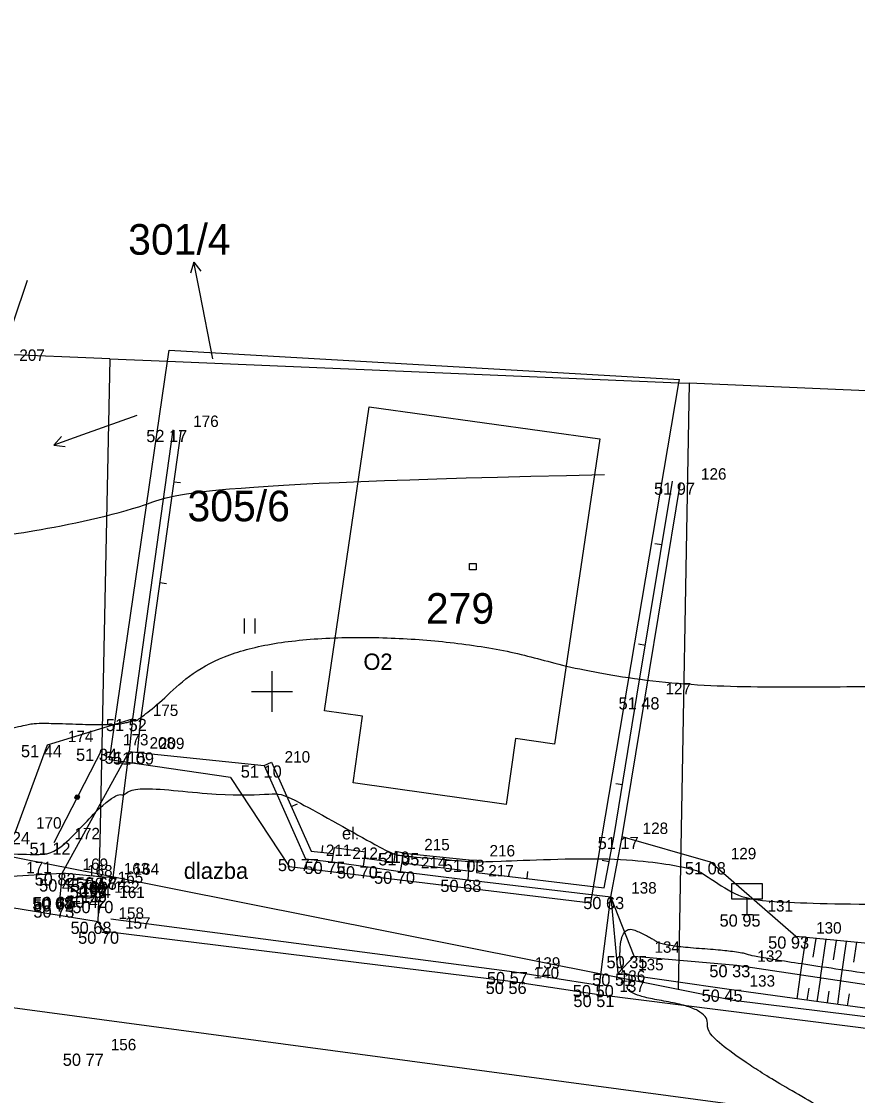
# Model space of a CAD drawing. Extents: x -704057 to -703795, y -1008732 to -1008584.
# Drawn here: x -703931.14 to -703910.66, y -1008659.9 to -1008633.59 of the extents above; entities that cross this region are included whole.
import ezdxf

# ---------------------------------------------------------------- set-up
doc = ezdxf.new("R2010")
doc.units = 0
for name, color, linetype in [('Z_body', 7, 'Continuous'), ('Z_body_cisla', 7, 'Continuous'), ('Z_body_vysky', 7, 'Continuous'), ('Z_chodnik', 7, 'Continuous'), ('Z_chody', 7, 'Continuous'), ('Z_dopravni_znaceni', 7, 'Continuous'), ('Z_hekt_sit', 7, 'Continuous'), ('Z_katastr_cisla_pozemkove', 7, 'Continuous'), ('Z_katastr_cisla_stavebni', 7, 'Continuous'), ('Z_katastr_hranice', 7, 'Continuous'), ('Z_katastr_hranice_KU', 7, 'Continuous'), ('Z_katastr_znacky', 7, 'Continuous'), ('Z_komunikace_zpevn_pl', 7, 'Continuous'), ('Z_oploceni', 7, 'Continuous'), ('Z_popis', 7, 'Continuous'), ('Z_propustek', 7, 'Continuous'), ('Z_rozhrani_zpevn', 7, 'Continuous'), ('Z_site_pilire', 7, 'Continuous'), ('Z_teren_hrany_paty', 7, 'Continuous'), ('Z_vrstevnice_popis', 7, 'Continuous'), ('Z_vrstevnice_vedlejsi', 7, 'Continuous'), ('Z_vstupy', 7, 'Continuous'), ('Z_zabradli', 7, 'Continuous'), ('Z_zelen_souvisla', 7, 'Continuous')]:
    doc.layers.add(name, color=color, linetype=linetype)

# ---------------------------------------------------------------- blocks, each defined once
blk = doc.blocks.new('POINT_DISPLAY')
blk.add_line((0, 0), (0, 0))
blk = doc.blocks.new('Z210')
blk.add_line((0, 0), (0, 0.17))
blk = doc.blocks.new('Z530')
for p, q in [((-0.05, 0.03), (-0.03, 0.05)), ((-0.05, -0.03), (-0.05, 0.03)), ((-0.03, 0.05), (0.03, 0.05)), ((-0.03, -0.03), (-0.03, 0.03)), ((-0.03, 0.03), (0.03, 0.03)), ((-0.03, -0.03), (0.03, 0.03)), ((0.03, 0.05), (0.05, 0.03)), ((0.03, 0.03), (0.03, -0.03)), ((0.05, 0.03), (0.05, -0.03)), ((-0.03, -0.05), (-0.05, -0.03)), ((0.03, -0.03), (-0.03, -0.03)), ((0.03, -0.05), (-0.03, -0.05)), ((0.05, -0.03), (0.03, -0.05))]:
    blk.add_line(p, q)
blk = doc.blocks.new('Z526')
for p, q in [((0.38, 0.75), (-0.38, 0.75)), ((-0.38, 0.75), (-0.38, 0.38)), ((0.38, 0.38), (0.38, 0.75)), ((-0.38, 0.38), (0.38, 0.38)), ((0, 0), (0, 0.38)), ((-0.13, 0), (0.13, 0))]:
    blk.add_line(p, q)
blk = doc.blocks.new('Z402')
for p, q in [((-0.03, 0.03), (0.05, 0.03)), ((-0.03, -0.05), (-0.03, 0.03)), ((0.05, 0.03), (0.05, -0.05)), ((0.05, -0.05), (-0.03, -0.05))]:
    blk.add_line(p, q)
blk = doc.blocks.new('Z61')
for p, q in [((0, 0.75), (-0.13, 0.5)), ((0, 0), (0, 0.75)), ((0, 0.75), (0.13, 0.5))]:
    blk.add_line(p, q)
blk = doc.blocks.new('Z306')
for p, q in [((-0.13, 0.17), (-0.13, -0.2)), ((0.13, 0.17), (0.13, -0.2))]:
    blk.add_line(p, q)

msp = doc.modelspace()

# ---------------------------------------------------------------- linework, layer by layer
at = {"layer": 'Z_chodnik'}
for p, q in [((-703928.89, -1008654.56), (-703928.5, -1008651.47)), ((-703916.98, -1008657.19), (-703916.7, -1008655.03)), ((-703929.26, -1008655.64), (-703929.24, -1008655.13)), ((-703916.99, -1008657.43), (-703916.98, -1008657.19))]:
    msp.add_line(p, q, dxfattribs=at)
at = {"layer": 'Z_chody'}
for p, q in [((-703921.81, -1008654.2), (-703920.19, -1008654.39)), ((-703921.85, -1008654.41), (-703920.2, -1008654.61))]:
    msp.add_line(p, q, dxfattribs=at)
at = {"layer": 'Z_hekt_sit'}
for p, q in [((-703925, -1008649.5), (-703925, -1008650.5)), ((-703925.5, -1008650), (-703924.5, -1008650))]:
    msp.add_line(p, q, dxfattribs=at)
at = {"layer": 'Z_katastr_cisla_pozemkove'}
for points in [[(-703926.45, -1008641.85), (-703926.77, -1008640.22)], [(-703928.31, -1008643.24), (-703929.64, -1008643.71)]]:
    msp.add_lwpolyline(points, dxfattribs=at)
at = {"layer": 'Z_katastr_hranice'}
for p, q in [((-703928.97, -1008641.85), (-703944.54, -1008641.19)), ((-703927.56, -1008641.91), (-703927.52, -1008641.64)), ((-703927.52, -1008641.64), (-703915.02, -1008642.36)), ((-703928.97, -1008641.85), (-703929.22, -1008653.69)), ((-703928.98, -1008651.67), (-703927.56, -1008641.91)), ((-703928.97, -1008641.85), (-703927.56, -1008641.91)), ((-703927.56, -1008641.91), (-703915.03, -1008642.44)), ((-703917.19, -1008655.18), (-703915.03, -1008642.44)), ((-703915.03, -1008642.44), (-703915.02, -1008642.36)), ((-703915.03, -1008642.44), (-703914.78, -1008642.45)), ((-703914.78, -1008642.45), (-703915.02, -1008655.64)), ((-703892.76, -1008643.39), (-703914.78, -1008642.45)), ((-703923.71, -1008650.47), (-703922.62, -1008643.03)), ((-703922.62, -1008643.03), (-703916.97, -1008643.81)), ((-703916.97, -1008643.81), (-703918.08, -1008651.29)), ((-703922.78, -1008650.6), (-703923.71, -1008650.47)), ((-703923.01, -1008652.24), (-703922.78, -1008650.6)), ((-703919.03, -1008651.15), (-703919.26, -1008652.77)), ((-703918.08, -1008651.29), (-703919.03, -1008651.15)), ((-703944.4, -1008651.45), (-703929.24, -1008654.47)), ((-703926.02, -1008652.11), (-703928.98, -1008651.67)), ((-703926.02, -1008652.11), (-703924.58, -1008654.29)), ((-703919.26, -1008652.77), (-703923.01, -1008652.24)), ((-703929.22, -1008653.69), (-703929.24, -1008654.47)), ((-703924.58, -1008654.29), (-703917.19, -1008655.18)), ((-703929.24, -1008654.47), (-703915.05, -1008657.29)), ((-703915.02, -1008655.64), (-703915.05, -1008657.29)), ((-703915.05, -1008657.29), (-703913.69, -1008657.56)), ((-703913.69, -1008657.56), (-703892.72, -1008660.17))]:
    msp.add_line(p, q, dxfattribs=at)
at = {"layer": 'Z_katastr_hranice_KU'}
msp.add_line((-703947.15, -1008655.63), (-703906.73, -1008661.04), dxfattribs=at)
at = {"layer": 'Z_komunikace_zpevn_pl'}
for p, q in [((-703929.26, -1008655.64), (-703940.41, -1008653.86)), ((-703929.1, -1008655.88), (-703929.26, -1008655.64)), ((-703919.09, -1008657.11), (-703929.1, -1008655.88)), ((-703916.99, -1008657.43), (-703919.09, -1008657.11)), ((-703906.05, -1008658.81), (-703916.99, -1008657.43))]:
    msp.add_line(p, q, dxfattribs=at)
at = {"layer": 'Z_oploceni'}
for p, q in [((-703927.43, -1008643.59), (-703928.42, -1008650.67)), ((-703927.23, -1008643.62), (-703928.22, -1008650.7)), ((-703916.06, -1008650.11), (-703915.19, -1008644.85)), ((-703915.86, -1008650.14), (-703914.99, -1008644.88)), ((-703916.62, -1008653.53), (-703916.06, -1008650.11)), ((-703916.42, -1008653.56), (-703915.86, -1008650.14)), ((-703928.42, -1008650.67), (-703928.5, -1008651.47)), ((-703928.22, -1008650.69), (-703928.3, -1008651.49)), ((-703928.5, -1008651.47), (-703928.27, -1008651.49)), ((-703925.19, -1008651.81), (-703925.01, -1008651.73)), ((-703925.19, -1008651.81), (-703924.18, -1008654.1)), ((-703925.01, -1008651.73), (-703924.04, -1008653.91)), ((-703916.86, -1008654.81), (-703916.62, -1008653.53)), ((-703916.7, -1008655.03), (-703916.42, -1008653.56)), ((-703924.04, -1008653.91), (-703923.5, -1008653.97)), ((-703922.01, -1008654.18), (-703921.97, -1008653.92)), ((-703921.77, -1008653.96), (-703921.97, -1008653.92)), ((-703921.85, -1008654.41), (-703921.77, -1008653.96)), ((-703924.18, -1008654.1), (-703923.53, -1008654.17)), ((-703922.76, -1008654.28), (-703921.85, -1008654.41)), ((-703922.73, -1008654.08), (-703922.01, -1008654.18)), ((-703920.17, -1008654.12), (-703920.2, -1008654.61)), ((-703920.17, -1008654.12), (-703919.97, -1008654.13)), ((-703919.97, -1008654.13), (-703919.99, -1008654.43)), ((-703919.99, -1008654.43), (-703916.86, -1008654.81)), ((-703920.2, -1008654.61), (-703916.7, -1008655.03))]:
    msp.add_line(p, q, dxfattribs=at)
at = {"layer": 'Z_propustek'}
for p, q in [((-703929.13, -1008654.55), (-703929.37, -1008655)), ((-703929.24, -1008655.13), (-703928.89, -1008654.56)), ((-703928.89, -1008654.56), (-703929.13, -1008654.55)), ((-703930.18, -1008655.09), (-703929.37, -1008655)), ((-703930.17, -1008655.24), (-703930.18, -1008655.09)), ((-703930.17, -1008655.24), (-703929.24, -1008655.13))]:
    msp.add_line(p, q, dxfattribs=at)
at = {"layer": 'Z_rozhrani_zpevn'}
for p, q in [((-703928.95, -1008655.57), (-703919.06, -1008656.87)), ((-703919.06, -1008656.87), (-703916.98, -1008657.19))]:
    msp.add_line(p, q, dxfattribs=at)
at = {"layer": 'Z_site_pilire'}
for p, q in [((-703923.48, -1008653.82), (-703923.53, -1008654.17)), ((-703923.48, -1008653.82), (-703922.71, -1008653.93)), ((-703922.76, -1008654.28), (-703922.71, -1008653.93)), ((-703923.53, -1008654.17), (-703922.76, -1008654.28))]:
    msp.add_line(p, q, dxfattribs=at)
at = {"layer": 'Z_teren_hrany_paty'}
for p, q in [((-703930.5, -1008651.31), (-703928.42, -1008650.67)), ((-703931.28, -1008653.44), (-703930.5, -1008651.31)), ((-703930.14, -1008654.45), (-703928.5, -1008651.47)), ((-703914.26, -1008654.18), (-703916.42, -1008653.56)), ((-703912.17, -1008656), (-703914.26, -1008654.18)), ((-703931.52, -1008654.53), (-703930.14, -1008654.45)), ((-703930.14, -1008654.45), (-703930.2, -1008655.04)), ((-703929.13, -1008654.55), (-703930.14, -1008654.45)), ((-703930.18, -1008655.09), (-703930.2, -1008655.04)), ((-703916.7, -1008655.03), (-703916.53, -1008656.91)), ((-703916.13, -1008656.48), (-703916.7, -1008655.03)), ((-703905.76, -1008656.62), (-703912.17, -1008656)), ((-703911.92, -1008656.02), (-703912.06, -1008656.93)), ((-703911.68, -1008656.05), (-703911.75, -1008656.51)), ((-703911.43, -1008656.07), (-703911.57, -1008657.01)), ((-703911.18, -1008656.1), (-703911.25, -1008656.57)), ((-703910.93, -1008656.12), (-703911.07, -1008657.08)), ((-703910.68, -1008656.14), (-703910.75, -1008656.63)), ((-703916.53, -1008656.91), (-703916.13, -1008656.48)), ((-703916.13, -1008656.48), (-703913.61, -1008656.7)), ((-703913.8, -1008657.3), (-703916.53, -1008656.91)), ((-703913.61, -1008656.7), (-703905.86, -1008657.87)), ((-703912.13, -1008657.53), (-703912.05, -1008656.94)), ((-703911.64, -1008657.6), (-703911.55, -1008657.01)), ((-703911.14, -1008657.66), (-703911.06, -1008657.09)), ((-703905.9, -1008658.38), (-703913.8, -1008657.3)), ((-703911.89, -1008657.56), (-703911.84, -1008657.27)), ((-703911.39, -1008657.63), (-703911.35, -1008657.34)), ((-703910.9, -1008657.7), (-703910.85, -1008657.41))]:
    msp.add_line(p, q, dxfattribs=at)
at = {"layer": 'Z_vrstevnice_popis'}
for points in [[(-703932.312, -1008646.249), (-703931.974, -1008646.22), (-703931.198, -1008646.162), (-703927.689, -1008645.442), (-703927.074, -1008644.896), (-703916.856, -1008644.687)], [(-703958.782, -1008656.452), (-703958.711, -1008656.345), (-703958.126, -1008655.591), (-703956.246, -1008655.482), (-703959.788, -1008654.246), (-703961.93, -1008651.293), (-703961.78, -1008651.126), (-703959.248, -1008651.187), (-703958.2, -1008651.305), (-703958.136, -1008651.315), (-703958.106, -1008651.318), (-703958.062, -1008651.325), (-703957.976, -1008651.334), (-703949.197, -1008652.35), (-703949.055, -1008652.366), (-703948.978, -1008652.372), (-703948.89, -1008652.368), (-703940.582, -1008653.06), (-703940.108, -1008653.095), (-703933.647, -1008653.758), (-703931.403, -1008653.997), (-703930.745, -1008653.985), (-703930.26, -1008654), (-703929.245, -1008652.825), (-703928.701, -1008652.453), (-703928.643, -1008652.6), (-703928.429, -1008652.279), (-703926.218, -1008652.574), (-703924.884, -1008652.504), (-703924.716, -1008652.484), (-703922.063, -1008653.995), (-703921.911, -1008654.006), (-703921.781, -1008654.024), (-703921.558, -1008654.048), (-703920.173, -1008654.162), (-703919.91, -1008654.188), (-703916.508, -1008654.023), (-703914.694, -1008654.331), (-703914.465, -1008654.432), (-703913.706, -1008654.968), (-703913.145, -1008655.151), (-703910.497, -1008655.228), (-703905.972, -1008655.203), (-703903.752, -1008655.504), (-703902.532, -1008655.695)]]:
    msp.add_open_spline(points, degree=3, dxfattribs=at)
at = {"layer": 'Z_vrstevnice_vedlejsi'}
for points in [[(-704009.362, -1008633.586), (-704007.915, -1008634.739), (-704007.143, -1008635.358), (-704002.876, -1008638.286), (-704002.679, -1008638.43), (-704002.255, -1008638.718), (-704001.165, -1008638.717), (-703995.889, -1008642.289), (-703994.89, -1008642.862), (-703994.417, -1008642.752), (-703993.832, -1008642.719), (-703993.258, -1008640.696), (-703993.341, -1008639.701), (-703993.272, -1008639.432), (-703993.04, -1008638.835), (-703992.99, -1008638.745), (-703990.403, -1008638.423), (-703989.481, -1008638.539), (-703989.058, -1008638.588), (-703989.018, -1008638.516), (-703988.578, -1008638.54), (-703988.475, -1008638.554), (-703988.362, -1008638.685), (-703988.319, -1008638.754), (-703988.294, -1008638.815), (-703986.637, -1008641.391), (-703986.518, -1008641.581), (-703985.267, -1008643.657), (-703984.422, -1008644.955), (-703982.223, -1008646.72), (-703982.083, -1008646.9), (-703980.47, -1008647.779), (-703979.335, -1008647.914), (-703971.793, -1008648.878), (-703969.312, -1008649.063), (-703968.076, -1008649.117), (-703960.948, -1008649.919), (-703959.282, -1008650.186), (-703958.493, -1008650.28), (-703957.367, -1008650.455), (-703955.116, -1008650.684), (-703950.816, -1008651.182), (-703948.3, -1008651.463), (-703946.953, -1008651.576), (-703945.397, -1008651.505), (-703943.023, -1008651.703), (-703939.161, -1008651.987), (-703938.27, -1008652.079), (-703937.191, -1008652.194), (-703934.147, -1008651.524), (-703931.028, -1008650.815), (-703930.717, -1008650.764), (-703928.94, -1008650.83), (-703928.501, -1008650.751), (-703928.424, -1008650.713), (-703928.413, -1008650.708), (-703928.266, -1008650.724), (-703926.027, -1008648.737), (-703920.5, -1008648.624), (-703915.824, -1008649.925), (-703908.88, -1008649.843), (-703904.651, -1008650.155), (-703897.103, -1008651.333), (-703893.743, -1008651.997), (-703889.99, -1008652.252), (-703881.693, -1008653.228), (-703874.656, -1008652.961), (-703868.448, -1008652.365), (-703859.857, -1008652.906), (-703856.36, -1008653.001), (-703843.765, -1008653.766), (-703842.17, -1008653.801), (-703841.143, -1008653.824), (-703831.904, -1008654.28)], [(-703930.067, -1008654.696), (-703930.045, -1008654.58), (-703929.834, -1008654.589), (-703929.209, -1008654.661), (-703929.296, -1008654.862), (-703929.333, -1008655.037), (-703929.576, -1008655.062), (-703929.586, -1008655.024), (-703929.626, -1008655.01), (-703930.062, -1008654.698), (-703930.067, -1008654.696)], [(-703944.218, -1008669.537), (-703942.215, -1008669.847), (-703941.835, -1008669.79), (-703940.983, -1008669.911), (-703940.538, -1008669.059), (-703940.441, -1008669.011), (-703939.659, -1008668.87), (-703938.392, -1008666.573), (-703937.218, -1008665.198), (-703936.994, -1008664.158), (-703936.811, -1008663.182), (-703935.504, -1008662.788), (-703930.851, -1008662.989), (-703930.683, -1008662.945), (-703930.514, -1008662.948), (-703928.53, -1008663.14), (-703926.451, -1008662.869), (-703924.285, -1008662.962), (-703918.453, -1008660.188), (-703917.529, -1008662.583), (-703908.804, -1008661.73), (-703914.417, -1008658.58), (-703914.255, -1008657.775), (-703916.458, -1008657.408), (-703916.075, -1008656.975), (-703916.505, -1008656.883), (-703916.435, -1008655.703), (-703915.746, -1008656.007), (-703915.438, -1008656.225), (-703913.541, -1008656.36), (-703913.202, -1008656.502), (-703907.93, -1008657.256), (-703905.824, -1008657.417), (-703900.033, -1008658.024), (-703894.345, -1008658.848), (-703890.179, -1008659.57), (-703887.702, -1008659.871), (-703882.266, -1008660.175), (-703878.347, -1008660.959), (-703873.149, -1008661.531), (-703869.803, -1008661.293), (-703867.148, -1008661.514), (-703856.66, -1008662.48), (-703848.555, -1008661.935), (-703843.582, -1008661.747), (-703840.018, -1008661.713), (-703835.656, -1008661.182), (-703832.168, -1008661.259), (-703831.497, -1008661.293), (-703819.488, -1008662.346), (-703817.521, -1008662.543), (-703807.841, -1008663.114), (-703805.78, -1008663.132)]]:
    msp.add_open_spline(points, degree=2, dxfattribs=at)
at = {"layer": 'Z_vstupy'}
for p, q in [((-703928.27, -1008651.49), (-703925.19, -1008651.81)), ((-703921.77, -1008653.96), (-703920.17, -1008654.12))]:
    msp.add_line(p, q, dxfattribs=at)
at = {"layer": 'Z_zabradli'}
msp.add_line((-703930.34, -1008653.7), (-703929.15, -1008651.4), dxfattribs=at)
at = {"layer": 'Z_zelen_souvisla'}
msp.add_line((-703931, -1008639.93), (-703931.69, -1008641.97), dxfattribs=at)

# ---------------------------------------------------------------- block references
at = {"layer": 'Z_body'}
for p in [(-703927.43, -1008643.59), (-703914.99, -1008644.88), (-703915.86, -1008650.14), (-703928.42, -1008650.67), (-703930.5, -1008651.31), (-703929.15, -1008651.4), (-703928.5, -1008651.47), (-703928.27, -1008651.49), (-703925.19, -1008651.81), (-703930.34, -1008653.7), (-703916.42, -1008653.56), (-703921.77, -1008653.96), (-703924.18, -1008654.1), (-703923.53, -1008654.17), (-703922.76, -1008654.28), (-703920.17, -1008654.12), (-703914.26, -1008654.18), (-703930.14, -1008654.45), (-703929.13, -1008654.55), (-703928.89, -1008654.56), (-703921.85, -1008654.41), (-703930.03, -1008654.6), (-703929.28, -1008654.76), (-703920.2, -1008654.61), (-703930.2, -1008655.04), (-703930.18, -1008655.09), (-703930.17, -1008655.03), (-703929.37, -1008655), (-703916.7, -1008655.03), (-703930.17, -1008655.24), (-703929.24, -1008655.13), (-703913.36, -1008655.46), (-703929.26, -1008655.64), (-703929.1, -1008655.88), (-703912.17, -1008656), (-703916.13, -1008656.48), (-703919.06, -1008656.87), (-703916.53, -1008656.91), (-703913.61, -1008656.7), (-703919.09, -1008657.11), (-703916.98, -1008657.19), (-703916.99, -1008657.43), (-703913.8, -1008657.3), (-703929.45, -1008658.87)]:
    msp.add_blockref('POINT_DISPLAY', p, dxfattribs=at)
at = {"layer": 'Z_dopravni_znaceni'}
msp.add_blockref('Z526', (-703913.36, -1008655.46), dxfattribs=at)
at = {"layer": 'Z_katastr_cisla_pozemkove'}
for p, rotation in [((-703926.77, -1008640.22), 11.3099), ((-703929.64, -1008643.71), 109.6538)]:
    msp.add_blockref('Z61', p, dxfattribs=dict(at, rotation=rotation))
at = {"layer": 'Z_katastr_znacky', "xscale": 2, "yscale": 2}
msp.add_blockref('Z402', (-703920.1, -1008646.92), dxfattribs=at)
at = {"layer": 'Z_oploceni'}
for p, rotation in [((-703927.41, -1008644.86), -97.99999999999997), ((-703915.45, -1008646.41), 80.6), ((-703927.75, -1008647.33), -97.99999999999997), ((-703915.85, -1008648.87), 80.6), ((-703916.41, -1008652.29), 80.69999999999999), ((-703924.53, -1008652.82), -66.19999999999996), ((-703923.77, -1008653.94), -6.100000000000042), ((-703922.37, -1008654.13), -8.100000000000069), ((-703916.74, -1008654.17), 79.2), ((-703918.75, -1008654.58), -6.80000000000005)]:
    msp.add_blockref('Z210', p, dxfattribs=dict(at, rotation=rotation))
at = {"layer": 'Z_popis'}
msp.add_blockref('Z306', (-703925.55, -1008648.38), dxfattribs=at)
at = {"layer": 'Z_zabradli', "rotation": 62.6}
msp.add_blockref('Z530', (-703929.77, -1008652.59), dxfattribs=at)

# ---------------------------------------------------------------- texts
at = {"layer": 'Z_body_cisla'}
for s, p in [('207', (-703931.19, -1008641.9)), ('176', (-703926.93, -1008643.52)), ('126', (-703914.49, -1008644.81)), ('127', (-703915.36, -1008650.07)), ('175', (-703927.92, -1008650.6)), ('174', (-703930, -1008651.24)), ('173', (-703928.65, -1008651.32)), ('208', (-703928, -1008651.4)), ('209', (-703927.77, -1008651.41)), ('210', (-703924.69, -1008651.74)), ('170', (-703930.78, -1008653.36)), ('128', (-703915.92, -1008653.49)), ('172', (-703929.84, -1008653.62)), ('211', (-703923.68, -1008654.03)), ('215', (-703921.27, -1008653.89)), ('216', (-703919.67, -1008654.04)), ('212', (-703923.03, -1008654.1)), ('213', (-703922.26, -1008654.2)), ('214', (-703921.35, -1008654.33)), ('129', (-703913.76, -1008654.11)), ('171', (-703931.02, -1008654.45)), ('169', (-703929.64, -1008654.37)), ('168', (-703929.53, -1008654.53)), ('163', (-703928.63, -1008654.48)), ('164', (-703928.39, -1008654.49)), ('217', (-703919.7, -1008654.53)), ('165', (-703928.78, -1008654.69)), ('166', (-703929.7, -1008654.96)), ('160', (-703929.68, -1008655.02)), ('167', (-703929.67, -1008654.95)), ('162', (-703928.87, -1008654.93)), ('161', (-703928.74, -1008655.06)), ('138', (-703916.2, -1008654.95)), ('159', (-703929.67, -1008655.16)), ('131', (-703912.86, -1008655.39)), ('158', (-703928.76, -1008655.57)), ('157', (-703928.6, -1008655.81)), ('130', (-703911.67, -1008655.93)), ('134', (-703915.63, -1008656.4)), ('132', (-703913.11, -1008656.62)), ('139', (-703918.56, -1008656.79)), ('135', (-703916.03, -1008656.83)), ('140', (-703918.59, -1008657.03)), ('136', (-703916.48, -1008657.11)), ('133', (-703913.3, -1008657.23)), ('137', (-703916.49, -1008657.36)), ('156', (-703928.95, -1008658.79))]:
    msp.add_text(s, height=0.28, dxfattribs=at).set_placement(p)
at = {"layer": 'Z_body_vysky'}
for s, p in [('52 17', (-703928.08, -1008643.89)), ('51 97', (-703915.64, -1008645.18)), ('51 48', (-703916.51, -1008650.44)), ('51 52', (-703929.07, -1008650.97)), ('51 44', (-703931.15, -1008651.61)), ('51 34', (-703929.8, -1008651.7)), ('51 15', (-703929.1, -1008651.77)), ('51 09', (-703928.895, -1008651.79)), ('51 10', (-703925.765, -1008652.11)), ('51 24', (-703931.93, -1008653.74)), ('51 12', (-703930.94, -1008654)), ('51 17', (-703917.02, -1008653.86)), ('51 05', (-703922.395, -1008654.26)), ('50 77', (-703924.855, -1008654.4)), ('50 75', (-703924.205, -1008654.47)), ('50 70', (-703923.41, -1008654.58)), ('51 03', (-703920.795, -1008654.42)), ('51 08', (-703914.885, -1008654.48)), ('50 82', (-703930.815, -1008654.75)), ('50 68', (-703929.805, -1008654.85)), ('50 74', (-703929.565, -1008654.86)), ('50 70', (-703922.5, -1008654.71)), ('50 45', (-703930.705, -1008654.9)), ('50 34', (-703929.955, -1008655.06)), ('50 68', (-703920.875, -1008654.91)), ('50 68', (-703930.875, -1008655.34)), ('50 72', (-703930.855, -1008655.39)), ('50 67', (-703930.845, -1008655.33)), ('50 42', (-703930.045, -1008655.3)), ('50 63', (-703917.375, -1008655.33)), ('50 73', (-703930.845, -1008655.54)), ('50 70', (-703929.89, -1008655.43)), ('50 95', (-703914.035, -1008655.76)), ('50 68', (-703929.935, -1008655.94)), ('50 70', (-703929.75, -1008656.18)), ('50 93', (-703912.845, -1008656.3)), ('50 35', (-703916.805, -1008656.78)), ('50 57', (-703919.735, -1008657.17)), ('50 51', (-703917.155, -1008657.21)), ('50 33', (-703914.285, -1008657)), ('50 56', (-703919.765, -1008657.41)), ('50 50', (-703917.63, -1008657.49)), ('50 51', (-703917.615, -1008657.73)), ('50 45', (-703914.475, -1008657.6)), ('50 77', (-703930.125, -1008659.17))]:
    msp.add_text(s, height=0.3, dxfattribs=at).set_placement(p)
at = {"layer": 'Z_katastr_cisla_pozemkove'}
for s, p in [('301/4', (-703928.523, -1008639.3)), ('305/6', (-703927.07, -1008645.83))]:
    msp.add_text(s, height=0.75, dxfattribs=at).set_placement(p)
at = {"layer": 'Z_katastr_cisla_stavebni'}
msp.add_text('279', height=0.75, dxfattribs=at).set_placement((-703921.23, -1008648.34))
at = {"layer": 'Z_popis'}
for s, height, p in [('O2', 0.4, (-703922.76, -1008649.47)), ('el.', 0.3, (-703923.285, -1008653.624)), ('dlazba', 0.4, (-703927.16, -1008654.59))]:
    msp.add_text(s, height=height, dxfattribs=at).set_placement(p)

doc.saveas('drawing.dxf')
